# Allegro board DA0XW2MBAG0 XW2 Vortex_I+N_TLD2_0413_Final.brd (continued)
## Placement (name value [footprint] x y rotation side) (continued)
L3610  *0_6/S  [S0603]  216.82 152.46 270 top
L3611  *0_6/S  [S0603]  207.93 154.24 0 top
L3612  *0_6/S  [S0603]  207.93 155.76 0 top
L3613  PBY160808T-221Y-N  [R0603]  203.87 155.76 0 top
L3614  PBY160808T-221Y-N  [R0603]  203.87 154.24 0 top
L3615  PBY160808T-221Y-N  [R0603]  219.36 155.25 90 top
L3616  PBY160808T-221Y-N  [R0603]  219.36 152.46 90 top
L4000  4.7UH,+-20%,650MA_1210  [CHOKE-LQH32PN4R7NN0L]  19.79 123.41 270 bottom
L4100  *DLP0NSN900HL2L  [CHOKE-DLP0NSN900HL2L]  337.39 59.12 180 bottom
L6000  *0_6/S  [S0603]  260.41 22.49 90 top
L7000  MCM2012B900GBE  [FILTER-MCM2012B900GBE-4P]  18.75 108.68 180 top
L7001  MCM2012B900GBE  [FILTER-MCM2012B900GBE-4P]  19.21 87.34 180 top
L7002  MCM2012B900GBE  [FILTER-MCM2012B900GBE-4P]  353.73 75.66 90 bottom
L8000  *DLP0NSN900HL2L  [CHOKE-DLP0NSN900HL2L]  337.22 119.09 0 bottom
L8001  0.68U +-20%5A  [CHOKE-PCMB041B-1R0MS]  354.87 114.77 90 bottom
L9000  *DLP0NSN900HL2L  [CHOKE-DLP0NSN900HL2L]  237.01 77.31 45 bottom
LED6000  LED 3P WHITE/AMBER  [LEDLTW-326DSKF-5A-3P-SMT]  364.98 152.71 270 top
LED9000  *White_19-113/T1D-CP2Q2HY/3T  [LED19-113-T1D-CP2Q2HY-3T]  130.59 113.5 270 top
LED9002  WHITE  [LEDLTW-C191DS5]  299.88 31.69 270 bottom
LED9003  WHITE  [LEDLTW-C191DS5]  269.93 45.15 90 bottom
LED9004  *LED 4P WHITE/YELLOW  [LEDLTST-C195KGJRKT-4P]  319.23 42.52 180 top
NOREF  -  []  160.31 14.19 0 top
NOREF#2  -  [unnamed#2]  358.5 16.02 0 top
NOREF#3  -  []  231.81 -42.07 0 top
NOREF#4  -  []  135.03 14.44 0 top
NOREF#5  -  [unnamed#2]  18.32 43.14 0 top
NOREF#6  -  []  54.01 -54.77 0 top
NOREF#7  -  [unnamed#2]  36.48 147.41 0 top
NOREF#8  -  []  131.6 14.44 180 bottom
NOREF#9  -  [unnamed#2]  358.5 16.02 180 bottom
NOREF#10  -  [unnamed#2]  14 43.78 180 bottom
NOREF#11  -  []  140.37 15.88 180 bottom
NOREF#12  -  [unnamed#2]  25.56 147.41 180 bottom
PAD2  *pad-mws-vn-2nmp  [PAD-MWS-VN-2NMP]  368.46 109.18 0 top
PAD3  *pad-mws-vn-3nmp  [PAD-MWS-VN-3NMP]  185.99 85.06 0 top
PAD4  *pad-mws-vn-4nmp  [PAD-MWS-VN-4NMP]  369.21 109.18 180 bottom
PAD5  *SPAD-RE317X60NP  [SPAD-RE317X60NP]  363.78 0.76 0 top
PAD6  *SPAD-RE79X322NP  [SPAD-RE79X322NP]  6.64 88.81 180 bottom
PAD7  *SPAD-RE79X322NP  [SPAD-RE79X322NP]  6.65 107.31 180 bottom
PAD8  *SPAD-RE79X922NP  [SPAD-RE79X922NP]  6.37 57.62 180 bottom
PAD9  *SPAD-RE317X59NP  [SPAD-RE317X59NP]  363.85 0.75 0 bottom
PAD10  *SPAD-RE47X512NP  [SPAD-RE47X512NP]  366.35 58.6 180 bottom
PAD11  *SPAD-RE79X393NP  [SPAD-RE79X393NP]  365.14 96.16 0 bottom
PAD12  *SPAD-RE79X185NP  [SPAD-RE79X185NP]  366.47 131.96 180 bottom
PAD13  *SPAD-RE79X185NP  [SPAD-RE79X185NP]  366.47 115.32 180 bottom
PAD15  *SPAD-C236NPP  [SPAD-C236NPP]  127.98 100.5 0 top
PAD18  *SPAD-C138NP  [SPAD-C138NP]  331.22 21.76 0 top
PAD19  *SPAD-C157NP  [SPAD-C157NP]  189.48 15 0 top
PAD20  *SPAD-XW2A-1NP  [SPAD-XW2A-1NP]  40 148 0 top
PAD21  *SPAD-RE79X282NP  [SPAD-RE79X282NP]  185.99 53.57 180 bottom
PC8001  4.7U/6.3V_6  [C0603]  236.51 144.97 0 bottom
PC8002  0.1u/25V_4  [C0402]  239.05 152.11 180 bottom
PC8003  *4.7u/25V_6  [C0603]  239.05 153.63 180 bottom
PC8004  *4.7u/25V_6  [C0603]  239.02 153.38 180 top
PC8005  2200P/50V_4  [C0402]  239.02 150.84 180 top
PC8006  0.1u/25V_4  [C0402]  239.02 151.86 180 top
PC8007  0.1u/25V_4  [C0402]  241.08 144.97 270 bottom
PC8008  0.1u/16V_4  [C0402]  233.46 138.62 0 bottom
PC8009  22u/6.3V_8  [C0805]  240.57 142.17 270 bottom
PC8010  *22u/6.3V_8  [C0805]  238.41 134.33 180 bottom
PC8011  22u/6.3V_8  [C0805]  238.28 142.17 270 bottom
PC8012  *22u/6.3V_8  [C0805]  236 142.17 270 bottom
PC8014  *2200p/50V_4  [C0402]  243.49 151.14 0 bottom
PC8015  *0.047u/16V_4  [C0402]  234.73 148.65 270 bottom
PC8016  0.01U/50V_4  [C0402]  235.36 146.24 0 bottom
PC8017  *0.047u/16V_4  [C0402]  232.32 148.43 90 top
PC9001  *4.7u/25V_6  [C0603]  216.31 61.94 270 top
PC9002  2.2U/10V_4  [C0402]  206.79 57.46 0 bottom
PC9003  *4.7u/25V_6  [C0603]  226.6 63.34 270 top
PC9004  *4.7u/25V_6  [C0603]  220.63 62.7 270 top
PC9006  0.1u/25V_4  [C0402]  224.7 58.99 180 bottom
PC9007  *15u/25V_7343H1.9  [CC7343]  205.87 62.96 90 top
PC9008  *15u/25V_7343H1.9  [CC7343]  210.6 62.96 90 top
PC9009  0.22u/25V_4  [C0402]  211.23 55.68 270 bottom
PC9010  *4.7u/25V_6  [C0603]  214.28 61.94 270 top
PC9011  2200P/50V_4  [C0402]  219.23 58.99 180 bottom
PC9013  1u/25V_6  [C0603]  208.82 46.92 270 bottom
PC9014  *2200p/50V_4  [C0402]  201.63 67.73 90 bottom
PC9015  *0.22u/10V_4  [C0402]  202.37 50.99 0 bottom
PC9017  *4.7u/25V_6  [C0603]  188.75 56.48 0 bottom
PC9018  *4.7u/25V_6  [C0603]  188.75 58.51 0 bottom
PC9019  *4.7u/25V_6  [C0603]  188.75 61.71 0 bottom
PC9020  0.22u/25V_4  [C0402]  203.87 55.81 270 bottom
PC9022  0.1u/25V_4  [C0402]  188.96 60.21 0 bottom
PC9023  2200P/50V_4  [C0402]  198.53 58.99 180 bottom
PC9024  0.1u/16V_4  [C0402]  208.82 49.21 90 bottom
PC9026  220u/2V_7343H1.9  [CC7343]  213.01 75.62 0 top
PC9027  220u/2V_7343H1.9  [CC7343]  203.61 81.34 180 bottom
PC9028  220u/2V_7343H1.9  [CC7343]  213.52 81.34 0 bottom
PC9029  *220u/2V_7343H1.9  [CC7343]  193.71 81.34 180 bottom
PC9030  *2200p/50V_4  [C0402]  194.09 65.5 180 top
PC9031  *1500p/50V_4  [C0402]  210.85 49.21 270 bottom
PC9032  1500p/50V_4  [C0402]  212.76 49.61 180 bottom
PC9033  56p/50V_4  [C0402]  204.5 49.46 0 bottom
PC9034  *100p/50V_4  [C0402]  205.39 48.45 180 bottom
PC9035  56p/50V_4  [C0402]  206.28 49.46 180 bottom
PC9037  *4.7u/25V_6  [C0603]  200.31 62.19 270 top
PC9038  *4.7u/25V_6  [C0603]  202.34 62.19 270 top
PC9040  0.1u/25V_4  [C0402]  211.61 58.99 180 bottom
PC9041  0.22u/25V_4  [C0402]  216.44 50.22 90 top
PC9042  *100p/50V_4  [C0402]  203.49 47.43 180 bottom
PC9043  220u/2V_7343H1.9  [CC7343]  192.44 76.54 180 top
PC9044  1u/6.3V_4  [C0402]  219.23 57.08 270 bottom
PC9045  *2200p/50V_4  [C0402]  215.3 65.5 180 bottom
PC9046  2200P/50V_4  [C0402]  199.93 56.61 90 top
PC9211  820p/50V_4  [C0402]  211.87 53.14 270 bottom
PC9501  0.1u/16V_4  [C0402]  192.41 83.89 270 top
PC9502  0.1u/16V_4  [C0402]  197.9 82.64 180 top
PC9503  *10u/6.3V_6  [C0603]  192.46 87.49 90 top
PC9504  0.1u/16V_4  [C0402]  193.4 85.31 90 top
PC9505  0.1u/16V_4  [C0402]  197.9 86.29 90 top
PC9506  *10u/6.3V_6  [C0603]  198.15 89.21 180 top
PC9507  0.1u/16V_4  [C0402]  195.61 81.59 270 top
PC9508  *820p/50V_4  [C0402]  194.09 81.97 0 top
PC9509  *0.1u/16V_4  [C0402]  197.64 81.27 90 top
PC9510  *1000P/50V_4  [C0402]  194.49 88.23 270 top
PC9511  *1000P/50V_4  [C0402]  195.94 88.46 0 top
PC9512  10u/6.3V_6  [C0603]  199.3 80.84 270 top
PC9513  0.1u/16V_4  [C0402]  204.25 83.83 180 top
PC9514  22u/6.3V_6  [C0603]  202.85 87.56 90 top
PC9515  0.1u/16V_4  [C0402]  202.72 85.28 90 top
PC9516  0.1u/16V_4  [C0402]  205.39 84.29 0 bottom
PC9801  *2.2u/50V_6  [C0603]  189.01 50 180 bottom
PC9802  *2.2u/50V_6  [C0603]  201.23 50.13 90 top
PC9803  *0.1u/16V_4  [C0402]  200.31 52.03 0 bottom
PC9804  *0.01u/16V_4  [C0402]  200.31 54.07 180 bottom
PC9805  *2.2U/10V_4  [C0402]  200.31 52.03 180 top
PC9806  *2.2u/50V_6  [C0603]  199.8 50.13 270 top
PC9807  *2.2u/50V_6  [C0603]  191.93 49.87 90 bottom
PC9808  *2.2U/10V_4  [C0402]  198.15 55.72 90 bottom
PC9809  *0.1u/16V_4  [C0402]  197.14 55.72 270 bottom
PC10000  1u/25V_4  [C0402]  344.23 138.77 270 top
PC10001  1u/25V_4  [C0402]  344.33 135.22 270 top
PC10002  0.1u/25V_4  [C0402]  353.6 145 90 bottom
PC10003  0.1u/25V_4  [C0402]  351.03 139.79 270 bottom
PC10004  1u/25V_4  [C0402]  345.85 146.52 180 top
PC11000  *1u/25V_6  [C0603]  255.56 14.31 180 top
PC11001  0.1u/25V_4  [C0402]  255.05 12.66 0 top
PC11003  1u/25V_6  [C0603]  253.78 11.77 90 bottom
PC11004  0.1u/25V_4  [C0402]  252.38 11.39 270 bottom
PC11005  0.1u/25V_4  [C0402]  252.38 13.15 270 bottom
PC11006  10u/25V_8  [C0805]  244.51 22.95 0 top
PC11007  2.2u/16V_6  [C0603]  245.09 17.04 270 bottom
PC11008  10u/25V_8  [C0805]  243.72 19.4 0 bottom
PC11009  2200P/50V_4  [C0402]  253.65 16.35 90 bottom
PC11010  0.1u/25V_4  [C0402]  252.64 16.35 270 bottom
PC11011  1u/25V_6  [C0603]  249 16.27 270 bottom
PC11012  0.047u/25V_4  [C0402]  247.81 16.85 90 bottom
PC11013  *1000P/50V_4  [C0402]  252.76 9.87 180 bottom
PC11017  68u/25V_7343H2.9  [CC7343-3H]  214.03 17.64 90 bottom
PC11018  0.1u/25V_4  [C0402]  216.97 19.5 270 bottom
PC11019  *2200p/50V_4  [C0402]  237.47 18.53 270 bottom
PC11020  0.1u/25V_4  [C0402]  238.79 8.65 0 top
PC11021  0.1u/25V_4  [C0402]  238.11 7.3 90 top
PC11022  0.1u/25V_4  [C0402]  239.53 6.69 90 top
PC11023  100p/50V_4  [C0402]  250.5 6.85 90 bottom
PC11024  0.1u/16V_4  [C0402]  236 8.85 0 top
PC11025  100p/50V_4  [C0402]  250.6 9.13 90 top
PC11026  100p/50V_4  [C0402]  249.08 8.02 270 top
PC11027  220p/50V_4  [C0402]  246.16 10.28 0 top
PC12001  100p/50V_4  [C0402]  258.78 21.55 180 bottom
PC12002  0.22u/6.3V_4  [C0402]  260.56 23.59 180 bottom
PC12003  0.1u/25V_4  [C0402]  211.23 5.55 0 bottom
PC12004  0.1u/25V_4  [C0402]  209.25 17.59 0 bottom
PC12005  2200P/50V_4  [C0402]  209.25 18.73 0 bottom
PC12006  100p/50V_4  [C0402]  219.11 6.95 90 bottom
PC12007  100p/50V_4  [C0402]  221.14 6.95 90 bottom
PC12008  3900p/50V_4  [C0402]  296.32 39.59 270 top
PC12009  *0.1u/16V_4  [C0402]  297.09 36.79 270 top
PC12010  *220p/50V_4  [C0402]  226.73 11.9 0 top
PC12011  *1u/6.3V_4  [C0402]  229.04 11.83 270 top
PC13000  2.2U/6.3V_4  [C0402]  197.64 35.65 180 bottom
PC13003  2200P/50V_4  [C0402]  201.68 40.6 270 bottom
PC13004  0.1u/25V_4  [C0402]  204.5 44.16 270 bottom
PC13005  0.1u/25V_4  [C0402]  205.01 34.05 0 top
PC13006  0.22u/25V_4  [C0402]  192.79 38.52 90 top
PC13007  1u/6.3V_4  [C0402]  199.3 41.62 180 bottom
PC13011  100u/6.3V_3528H1.9  [C3528]  189.41 42.81 270 bottom
PC13012  0.1u/16V_4  [C0402]  189.52 38.95 180 bottom
PC13013  *2200p/50V_4  [C0402]  197.77 37.43 270 top
PC13014  *0.1u/16V_4  [C0402]  200.69 42.38 90 bottom
PC13015  2.2U/6.3V_4  [C0402]  220.12 46.7 0 bottom
PC13016  *4.7u/25V_6  [C0603]  214.92 43.68 270 bottom
PC13017  *4.7u/25V_6  [C0603]  213.47 43.68 270 bottom
PC13018  2200P/50V_4  [C0402]  216.14 44.03 270 bottom
PC13019  0.1u/25V_4  [C0402]  211.08 44.01 270 bottom
PC13020  0.1u/25V_4  [C0402]  210.06 44.01 270 bottom
PC13021  1u/6.3V_4  [C0402]  219.11 41.11 0 bottom
PC13022  0.22u/25V_4  [C0402]  220.78 43.4 270 bottom
PC13023  22u/6.3V_8  [C0805]  227.36 51.87 180 bottom
PC13024  22u/6.3V_8  [C0805]  222.79 53.81 0 bottom
PC13025  *22u/6.3V_8  [C0805]  220.25 48.96 0 bottom
PC13026  0.1u/16V_4  [C0402]  228.24 50.36 0 bottom
PC13027  22u/6.3V_8  [C0805]  222.79 51.78 0 bottom
PC13028  *200P/50V_4  [C0402]  217.3 44.92 90 top
PC13029  *0.1u/16V_4  [C0402]  217.71 40.48 270 bottom
PC13030  *4.7u/25V_6  [C0603]  207.88 38.37 180 bottom
PC13031  *4.7u/25V_6  [C0603]  209.33 35.73 270 bottom
PC13032  2200P/50V_4  [C0402]  207.42 36.79 0 bottom
PC13033  0.1u/25V_4  [C0402]  208.57 39.84 0 bottom
PC13034  0.1u/25V_4  [C0402]  210.09 40.22 90 bottom
PC13035  4.7U/6.3V_6  [C0603]  215.96 32.22 270 bottom
PC13036  0.1u/25V_4  [C0402]  216.06 34.63 180 top
PC13040  0.1u/16V_4  [C0402]  223.81 34.51 90 top
PC13041  100u/6.3V_3528H1.9  [C3528]  227.77 36.49 180 bottom
PC13042  *2200p/50V_4  [C0402]  212.25 39.97 270 bottom
PC13043  *0.1u/16V_4  [C0402]  213.65 32.09 270 bottom
PC13044  0.1u/16V_4  [C0402]  214.66 32.09 90 bottom
PC14000  1U/6.3V_4  [C0402]  95.03 64.73 90 top
PC14001  0.1U/25V_4  [C0402]  73.77 51.81 0 top
PC14002  0.1U/25V_4  [C0402]  97.95 66.64 180 top
PC14003  *4.7u/25V_6  [C0603]  97.95 69.18 0 top
PC14004  *4.7u/25V_6  [C0603]  97.95 71.21 0 top
PC14005  2200P/50V_4  [C0402]  97.95 67.65 180 top
PC14006  0.22u/25V_4  [C0402]  103.28 60.97 0 top
PC14007  68P/50V_4  [C0402]  91.9 66.46 270 top
PC14008  10U/6.3V_6  [C0603]  93.76 64.23 270 top
PC14009  0.1U/16V_4  [C0402]  102.75 49.54 0 top
PC14010  22U/6.3V_8  [C0805]  102.9 46.75 180 top
PC14011  *22U/6.3V_8  [C0805]  96.76 50.21 0 top
PC14012  *22U/6.3V_8  [C0805]  96.76 48.15 0 top
PC14013  *22u/6.3V_8  [C0805]  96.78 46.14 0 top
PC14014  0.1U/16V_4  [C0402]  92.74 61.94 270 top
PC14015  *0.033U/10V_4  [C0402]  94.39 62.32 0 top
PC14016  *2200P/50V_4  [C0402]  98.33 65.5 90 bottom
PC14017  *0.1U/16V_4  [C0402]  101.63 69.81 0 top
PC14018  1u/6.3V_4  [C0402]  101.63 67.78 0 top
PC14019  *220P/50V_4  [C0402]  101.63 65.75 180 top
PC15000  1U/6.3V_4  [C0402]  206.53 31.43 0 bottom
PC15001  0.1U/25V_4  [C0402]  208.9 28.51 270 bottom
PC15002  *4.7u/25V_6  [C0603]  215.02 26.38 90 bottom
PC15003  0.1U/25V_4  [C0402]  214.54 29.17 270 bottom
PC15004  *4.7u/25V_6  [C0603]  216.47 26.38 90 bottom
PC15005  2200P/50V_4  [C0402]  213.52 29.17 90 bottom
PC15006  0.22u/25V_4  [C0402]  202.34 30.54 90 bottom
PC15007  0.22U/10V_4  [C0402]  206.41 24.19 180 bottom
PC15008  0.1U/16V_4  [C0402]  190.41 26.63 90 bottom
PC15009  22U/6.3V_8  [C0805]  191.42 34.05 270 bottom
PC15010  *22U/6.3V_8  [C0805]  193.99 26.61 90 bottom
PC15011  *22U/6.3V_8  [C0805]  191.95 26.61 90 bottom
PC15012  *2200P/50V_4  [C0402]  203.87 32.48 90 top
PC16000  1U/6.3V_4  [C0402]  291.73 15.51 90 top
PC16001  *4.7u/25V_6  [C0603]  294.65 8.98 180 top
PC16002  2200P/50V_4  [C0402]  294.62 12.46 0 top
PC16003  0.1U/25V_4  [C0402]  296.83 8.5 270 top
PC16004  0.1U/25V_4  [C0402]  294.62 13.43 0 top
PC16005  *4.7u/25V_6  [C0603]  294.65 10.99 180 top
PC16006  0.22u/25V_4  [C0402]  291.57 19.7 270 top
PC16007  0.1U/16V_4  [C0402]  291.24 26 0 top
PC16008  22U/6.3V_8  [C0805]  292.13 23.84 90 top
PC16009  *22U/6.3V_8  [C0805]  294.8 23.84 90 bottom
PC16010  *22U/6.3V_8  [C0805]  292.77 23.84 90 bottom
PC16011  *2200P/50V_4  [C0402]  295.13 14.87 270 bottom
PC16012  *0.1U/16V_4  [C0402]  297.8 14.49 270 top
PC16013  0.1u/16V_4  [C0402]  103.28 21.55 270 top
PC16014  10u/6.3V_6  [C0603]  104.55 21.55 90 top
PC16015  *10u/6.3V_6  [C0603]  105.16 33.11 180 top
PC16016  0.1u/16V_4  [C0402]  105.42 36.03 0 top
PC16017  *0.1u/16V_4  [C0402]  101.94 22.09 270 top
PC16018  10U/6.3V_6  [C0603]  105.16 34.63 180 top
PC16019  1u/6.3V_4  [C0402]  105.82 28.28 270 top
PC17000  1U/6.3V_4  [C0402]  181.9 150.2 270 bottom
PC17001  0.1U/25V_4  [C0402]  184.82 152.87 0 bottom
PC17002  *4.7u/25V_6  [C0603]  184.31 157.44 180 bottom
PC17003  *4.7u/25V_6  [C0603]  184.31 155.41 180 bottom
PC17004  0.1U/25V_4  [C0402]  180.88 157.44 180 bottom
PC17005  2200P/50V_4  [C0402]  184.82 153.89 0 bottom
PC17006  *0.1U/16V_4  [C0402]  188.63 151.35 180 bottom
PC17007  0.22u/25V_4  [C0402]  181.64 146.52 90 bottom
PC17008  0.1U/16V_4  [C0402]  190.91 130.49 0 bottom
PC17009  22U/6.3V_8  [C0805]  190.1 139.05 180 bottom
PC17010  *22U/6.3V_8  [C0805]  190.1 136.77 180 bottom
PC17011  *22U/6.3V_8  [C0805]  191.55 132.04 180 bottom
PC17012  *2200P/50V_4  [C0402]  184.94 151.47 90 top
PC18000  4.7u/6.3V_6  [C0603]  304.58 61.3 270 top
PC18001  2200p/50V_4  [C0402]  307.63 69.43 90 top
PC18002  0.1u/25V_4  [C0402]  306.61 69.43 90 top
PC18003  *4.7u/25V_6  [C0603]  309.15 69.18 270 top
PC18004  *4.7u/25V_6  [C0603]  311.18 69.18 270 top
PC18005  0.1u/25V_4  [C0402]  311.89 63.34 180 top
PC18006  0.1u/25V_4  [C0402]  300.26 62.45 270 top
PC18007  0.1u/16V_4  [C0402]  291.75 61.86 90 top
PC18008  22u/6.3V_8  [C0805]  290.48 67.02 270 bottom
PC18009  22u/6.3V_8  [C0805]  290.48 67.02 270 top
PC18010  22u/6.3V_8  [C0805]  288.45 67.02 270 top
PC18011  *22u/6.3V_8  [C0805]  285.15 64.48 0 top
PC18012  22u/6.3V_8  [C0805]  290.23 61.94 90 top
PC18013  *2200p/50V_4  [C0402]  301.91 66.13 90 bottom
PC18014  0.1u/16V_4  [C0402]  307.88 63.84 0 top
PC18015  0.1u/16V_4  [C0402]  305.8 61.61 90 top
PC19000  4.7u/6.3V_4  [C0402_2]  132.62 148.17 90 bottom
PC19001  0.1u/16V_4  [C0402]  123.35 154.01 270 top
PC19002  0.1u/16V_4  [C0402]  130.84 152.62 180 top
PC19003  1u/6.3V_4  [C0402]  124.37 154.01 90 bottom
PC19004  0.01U/50V_4  [C0402]  131.99 146.78 0 bottom
PC19005  *0.1u/16V_4  [C0402]  131.93 151.47 270 bottom
PC19006  *0.1u/6.3V_2  [C0201]  126.65 141.65 180 bottom
PC19007  *0.1u/16V_4  [C0402]  131.96 153.25 270 bottom
PC19008  *0.1u/6.3V_2  [C0201]  124.24 141.01 270 bottom
PC19009  220p/50V_4  [C0402]  126.14 146.39 90 top
PC19010  220p/50V_4  [C0402]  124.75 146.9 0 top
PC19011  47p/50V_4  [C0402]  124.75 149.95 0 top
PC19012  *0.1u/16V_4  [C0402]  121.19 144.11 90 bottom
PC19013  330p/50V_4  [C0402]  129.83 148.81 180 top
PC19014  1u/6.3V_4  [C0402]  133.76 146.78 0 bottom
PC20000  1u/6.3V_4  [C0402]  140.62 153.51 270 top
PC20001  *4.7u/25V_6  [C0603]  136.94 146.9 180 top
PC20002  *4.7u/25V_6  [C0603]  144.3 149.7 90 top
PC20003  *4.7u/25V_6  [C0603]  142.27 149.7 90 top
PC20004  2200P/50V_4  [C0402]  143.54 149.44 90 bottom
PC20005  0.1u/50V_4  [C0402]  142.58 149.44 90 bottom
PC20006  68u/25V_7343H2.9  [CC7343-3H]  147.58 156.91 0 bottom
PC20007  68u/25V_7343H2.9  [CC7343-3H]  164.55 157.06 0 bottom
PC20008  68u/25V_7343H2.9  [CC7343-3H]  172.63 155.08 270 bottom
PC20009  0.1u/50V_4  [C0402]  145.83 154.49 90 top
PC20010  *2200p/50V_4  [C0402]  141.51 145.76 180 top
PC20011  0.22u/25V_4  [C0402]  140.67 141.95 180 top
PC20012  *0.1u/50V_4  [C0402]  141.64 159.35 180 top
PC20013  *4.7u/25V_6  [C0603]  155.4 149.28 90 top
PC20014  *4.7u/25V_6  [C0603]  138.26 150 90 top
PC20015  *4.7u/25V_6  [C0603]  152.31 149.32 90 top
PC20016  2200P/50V_4  [C0402]  150.65 149.66 90 top
PC20017  0.1u/50V_4  [C0402]  149.64 149.66 90 top
PC20018  1u/6.3V_4  [C0402]  148.11 154.62 270 top
PC20019  0.1u/50V_4  [C0402]  153.83 154.49 90 top
PC20020  *2200p/50V_4  [C0402]  150.02 145.51 180 top
PC20021  0.22u/25V_4  [C0402]  149.89 141.54 90 top
PC20022  *0.1u/50V_4  [C0402]  148.62 159.06 180 top
PC20023  220u/2V_7343H1.9  [CC7343]  167.67 133.57 0 bottom
PC20024  220u/2V_7343H1.9  [CC7343]  158.02 133.57 180 bottom
PC20025  220u/2V_7343H1.9  [CC7343]  148.37 133.57 180 bottom
PC20026  220u/2V_7343H1.9  [CC7343]  171.86 133.54 0 top
PC20027  *4.7u/25V_6  [C0603]  162.16 149.44 90 top
PC20028  *4.7u/25V_6  [C0603]  169.45 149.44 90 top
PC20029  *4.7u/25V_6  [C0603]  160.18 149.44 90 top
PC20030  2200P/50V_4  [C0402]  160.56 149.44 90 bottom
PC20031  0.1u/50V_4  [C0402]  161.58 149.44 90 bottom
PC20032  1u/6.3V_4  [C0402]  155.99 154.62 270 top
PC20033  0.1u/50V_4  [C0402]  161.7 154.49 90 top
PC20034  *2200p/50V_4  [C0402]  158.4 145.51 180 top
PC20035  0.22u/25V_4  [C0402]  158.78 141.54 90 top
PC20036  *0.1u/50V_4  [C0402]  156.5 159.06 180 top
PC20037  *4.7u/25V_6  [C0603]  164.62 149.41 90 top
PC20038  *4.7u/25V_6  [C0603]  173.51 149.16 90 top
PC20039  *4.7u/25V_6  [C0603]  171.48 149.16 90 top
PC20040  2200P/50V_4  [C0402]  170.59 149.44 90 bottom
PC20041  0.1u/50V_4  [C0402]  169.58 149.44 90 bottom
PC20042  1u/6.3V_4  [C0402]  164.12 154.62 270 top
PC20043  0.1u/50V_4  [C0402]  169.83 154.49 90 top
PC20044  *2200p/50V_4  [C0402]  168.18 145.51 180 top
PC20045  0.22u/25V_4  [C0402]  167.93 141.41 90 top
PC20046  *0.1u/50V_4  [C0402]  164.62 159.06 180 top
PC20047  *0.1u/16V_4  [C0402]  184.82 153.13 0 top
PC21000  10u/25V_8  [C0805]  118.52 123.97 90 bottom
PC21001  10u/25V_8  [C0805]  116.49 123.97 90 bottom
PC21003  *10u/25V_8  [C0805]  118.7 123.94 90 top
PC21004  1u/25V_4  [C0402]  124.62 125.19 90 bottom
PC21005  2200P/50V_4  [C0402]  116.87 126.07 0 bottom
PC21006  0.1u/50V_4  [C0402]  116.87 127.09 0 bottom
PC21007  68u/25V_7343H2.9  [CC7343-3H]  116.97 117.64 90 bottom
PC21008  *15u/25V_7343H1.9  [CC7343]  121.83 134.36 90 bottom
PC21009  1u/6.3V_4  [C0402]  122.97 126.96 180 bottom
PC21010  1u/25V_4  [C0402]  125.13 126.58 180 bottom
PC21011  *2200p/50V_4  [C0402]  122.71 118.96 270 bottom
PC21012  *10u/25V_8  [C0805]  119.51 112.03 90 top
PC21013  10u/25V_8  [C0805]  119.51 112.03 90 bottom
PC21015  10u/25V_8  [C0805]  117.53 111.01 90 bottom
PC21016  1u/25V_4  [C0402]  125.46 113.12 90 bottom
PC21017  2200P/50V_4  [C0402]  114.89 112.05 90 bottom
PC21018  0.1u/50V_4  [C0402]  115.91 111.67 90 bottom
PC21019  220u/2V_7343H1.9  [CC7343]  128.3 123.53 180 top
PC21020  220u/2V_7343H1.9  [CC7343]  129.45 117.44 180 bottom
PC21021  1u/6.3V_4  [C0402]  123.73 114.9 180 bottom
PC21022  1u/25V_4  [C0402]  126.12 114.59 180 bottom
PC21023  *2200p/50V_4  [C0402]  125.51 107.53 0 bottom
PC21024  10u/25V_8  [C0805]  176.94 152.01 0 bottom
PC21025  10u/25V_8  [C0805]  176.94 154.01 0 bottom
PC21026  1u/25V_4  [C0402]  177.71 145.93 0 bottom
PC21027  2200P/50V_4  [C0402]  176.94 156.55 0 bottom
PC21028  0.1u/50V_4  [C0402]  176.94 155.54 0 bottom
PC21029  1u/6.3V_4  [C0402]  179.99 147.25 0 bottom
PC21030  1u/25V_4  [C0402]  179.1 145.55 90 bottom
PC21031  22u/6.3V_8  [C0805]  178.47 130.77 180 bottom
PC21032  22u/6.3V_8  [C0805]  178.42 132.81 180 bottom
PC21033  *22u/6.3V_8  [C0805]  174.4 132.68 0 bottom
PC21034  *22u/6.3V_8  [C0805]  174.4 134.71 0 bottom
PC21035  *2200p/50V_4  [C0402]  173.82 148.39 180 bottom
PC22000  0.1U/16V_4  [C0402]  38.13 62.7 270 top
PC22001  0.1U/16V_4  [C0402]  282.1 34.51 270 top
PC22002  0.1U/16V_4  [C0402]  286.67 34.63 270 top
PC22003  0.1U/16V_4  [C0402]  42.7 62.7 270 top
PC22004  *10U/6.3V_6  [C0603]  282.1 38.95 0 top
PC22005  0.1U/16V_4  [C0402]  281.97 37.68 0 top
PC22006  0.1U/16V_4  [C0402]  286.8 37.68 180 top
PC22007  *10U/6.3V_6  [C0603]  286.8 38.95 180 top
PC22008  *10U/6.3V_6  [C0603]  38.01 66.51 0 top
PC22009  0.1U/16V_4  [C0402]  38.13 64.48 90 top
PC22010  0.1U/16V_4  [C0402]  42.7 64.48 90 top
PC22011  *10U/6.3V_6  [C0603]  42.96 66.13 180 top
PC22012  0.1U/16V_4  [C0402]  284.39 31.71 90 top
PC22013  0.1U/16V_4  [C0402]  40.42 59.91 90 top
PC22014  *0.1U/16V_4  [C0402]  285.91 32.09 180 top
PC22015  *0.1U/16V_4  [C0402]  41.94 60.29 180 top
PC22016  1000P/50V_4  [C0402]  284 38.27 270 top
PC22017  1000P/50V_4  [C0402]  284.97 38.27 270 top
PC22018  *0.1U/16V_4  [C0402]  38.77 60.39 0 top
PC22019  1000P/50V_4  [C0402]  39.91 67.02 270 top
PC22020  1000P/50V_4  [C0402]  40.93 67.02 270 top
PC22021  *0.1U/16V_4  [C0402]  282.86 32.09 0 top
PC22022  *0.1U/16V_4  [C0402]  263.68 37.68 90 top
PC22023  0.1U/16V_4  [C0402]  266.61 40.73 270 top
PC22024  0.1U/16V_4  [C0402]  264.83 37.68 90 top
PC22025  0.1U/16V_4  [C0402]  266.73 43.52 180 top
PC22026  0.1U/16V_4  [C0402]  262.03 40.73 270 top
PC22027  1000P/50V_4  [C0402]  263.86 45.05 270 top
PC22028  1000P/50V_4  [C0402]  264.83 45.05 270 top
PC22029  *0.1U/16V_4  [C0402]  265.84 37.68 90 top
PC22030  *10U/6.3V_6  [C0603]  263.68 47.08 180 top
PC22031  0.1U/16V_4  [C0402]  261.07 41.75 90 top
PC22032  *10U/6.3V_6  [C0603]  266.73 45.18 180 top
PC23005  0.1U/16V_4  [C0402]  190.23 134.89 180 top
PC23006  0.1U/16V_4  [C0402]  190.28 140.88 180 top
PC23007  0.1U/16V_4  [C0402]  187.26 141.21 270 top
PC23008  *10U/6.3V_6  [C0603]  188.5 140.76 270 top
PC23009  0.1U/16V_4  [C0402]  112.17 96.32 180 bottom
PC23010  *10U/6.3V_6  [C0603]  112.3 97.88 180 bottom
PC23011  0.1U/16V_4  [C0402]  122.21 91.25 0 top
PC23012  0.1U/16V_4  [C0402]  119.29 93.56 270 top
PC23013  *10U/6.3V_6  [C0603]  117.89 93.82 270 top
PC23014  0.1U/16V_4  [C0402]  203.23 11.06 270 bottom
PC23015  0.1U/16V_4  [C0402]  196.5 15.79 90 bottom
PC23016  *10U/6.3V_6  [C0603]  205.82 9.79 180 bottom
PC23017  1u/6.3V_4  [C0402]  199.88 13.15 0 bottom
PC23018  *0.1u/16V_4  [C0402]  198.86 15.64 90 bottom
PC24000  *0.1U/16V_4  [C0402]  191.55 158.08 270 top
PC25000  1000P/50V_4  [C0402]  297.21 35.65 180 bottom
PC25001  0.22U/10V_4  [C0402]  295.18 34.63 0 bottom
PC25002  3300P/50V_4  [C0402]  293.78 44.57 0 bottom
PC25003  0.1U/16V_4  [C0402]  299.47 40.48 270 bottom
PC25004  *0.01U/50V_4  [C0402]  299.24 35.65 0 bottom
PC25005  1U/6.3V_4  [C0402]  270.03 40.6 90 bottom
PC25007  *220u/2.5V_3528H1.9  [C3528]  237.27 137.12 180 bottom
PC25008  0.1u/25V_4  [C0402]  346.23 139.05 90 top
PC25009  0.1u/25V_4  [C0402]  332.95 137.99 90 bottom
PC25010  *15u/25V_3528H1.1  [C3528]  244.74 20.16 0 top
PC25011  15u/25V_3528H1.1  [C3528]  211.11 27.14 90 bottom
PC25012  15u/25V_3528H1.1  [C3528]  102.5 78.5 180 top
PC25013  *15u/25V_3528H1.1  [C3528]  203.87 38.7 90 bottom
PC25014  0.1u/16V_4  [C0402]  227.92 85.05 270 bottom
PCN10000  040003HR005BA19ZL  [DCJK-040003HR005BA19ZL-5P]  362.74 145.06 90 top
PCN12000  C144RN-K0823-L  [BAT-C144RN-K0823-L-8P-L-SMT]  221.73 2.2 180 bottom
PD1  P4SMAFJ20A  [D-3_8X2_5]  346.49 142.48 90 bottom
PD2  PDZ5.1B  [DSM]  332.26 145.2 0 bottom
PD3  PDZ5.1B  [DSM]  332.69 142.58 90 top
PD9002  RB500V-40  [DSM]  214.96 52.26 90 top
PD9005  RB500V-40  [DSM]  213.18 52.26 90 top
PD9501  *RB500V-40  [DSM]  198.51 84.88 180 bottom
PD11000  P4SMAFJ20A  [D-3_8X2_5]  303.03 7.41 0 top
PD11001  MEW316-D3-G  [DSM]  252 14.15 0 top
PD11002  *UDZ8V2B-7  [DSM]  244.55 17.37 180 top
PD11003  MEW316-D3-G  [DSM]  252 16.05 0 top
PD11004  SX34  [D-4_3X2_7]  210.67 7.76 180 bottom
PD11005  MEW316-D3-G  [DSM]  252.18 14.66 0 bottom
PD11006  PDZ5.1B  [DSM]  220.88 20.89 90 top
PD11007  MEW316-D3-G  [DSM]  255.43 10.25 0 top
PD11008  BAT54CW  [UMT_213-3-1_3]  257.33 7.84 0 top
PD12000  BAV99-7-F  [SOT23_213-3_3-2]  223.93 9.74 90 bottom
PD12001  BAV99-7-F  [SOT23_213-3_3-2]  220.12 9.74 90 bottom
PD25000  BAT54AW-L  [SOT323_213-2_1-1_3-3P]  294.8 30.57 270 bottom
PJP13001  *POWER_JP/S  [SHORT-SOLDERJUMPER-3]  225.97 52.92 270 bottom
PJP13002  *POWER_JP/S  [SHORT-SOLDERJUMPER-3]  224.44 39.89 180 bottom
PJP14000  *POWER_JP/S  [SHORT-SOLDERJUMPER-3]  99.73 44.54 270 top
PJP15000  *POWER_JP/S  [SHORT-SOLDERJUMPER-3]  190.15 30.85 180 bottom
PJP16000  *POWER_JP/S  [SHORT-SOLDERJUMPER-3]  291.39 28.21 180 top
PJP16001  *POWER_JP/S  [SHORT-SOLDERJUMPER-3]  102.27 36.79 180 top
PJP17000  *POWER_JP/S  [SHORT-SOLDERJUMPER-3]  188.63 131.25 45 bottom
PJP18000  *short-solderjumper-3  [SHORT-SOLDERJUMPER-3]  285.15 66.77 315 top
PL2100  0.47uH_7x7x3  [CHOKE-PCMC063T-3R3MN-SMT]  129.67 123.23 0 bottom
PL2101  0.47uH_7x7x3  [CHOKE-PCMC063T-3R3MN-SMT]  130.59 111.67 0 bottom
PL2102  0.68uH_7x7x3  [CHOKE-PCMC063T-3R3MN-SMT]  175.67 140.9 270 bottom
PL8001  0.68uH_7x7x3  [CHOKE-PCMC063T-3R3MN-SMT]  245.02 145.42 270 bottom
PL9001  0.22uH_7x7x3  [CHOKE-PCMC063T-3R3MN-SMT]  205.7 72.63 90 bottom
PL9004  0.22uH_7x7x3  [CHOKE-PCMC063T-3R3MN-SMT]  195.38 72.66 90 bottom
PL9005  0.22uH_7x7x3  [CHOKE-PCMC063T-3R3MN-SMT]  214.33 72.61 90 bottom
PL9501  2.2uH_2.5x2.0x1.2  [L2_5X2-1_2H]  200.44 85.02 0 top
PL11000  2.2uH_10x10x4  [L10X10-3_8]  228.38 18.12 180 bottom
PL12000  *Short_0805  [S0805]  217.13 5.91 270 bottom
PL12001  *Short_0805  [S0805]  215.14 5.91 270 bottom
PL12002  *Short_0805  [S0805]  213.19 5.91 270 bottom
PL13001  2.2uH_7x7x3  [CHOKE-PCMC063T-3R3MN-SMT]  194.6 39.74 90 bottom
PL13002  *0_8/S  [S0805]  211.11 42.13 0 bottom
PL13003  2.2uH_7x7x3  [CHOKE-PCMC063T-3R3MN-SMT]  225.33 46.19 90 bottom
PL13004  *Short_0805  [S0805]  205.65 40.1 0 bottom
PL13005  1.5uH_7x7x3  [CHOKE-PCMC063T-3R3MN-SMT]  220.63 35.65 0 bottom
PL14001  1uH_7x7x3  [CHOKE-PCMC063T-3R3MN-SMT]  100.49 55.72 270 top
PL15001  2.2uH_7x7x3  [CHOKE-PCMC063T-3R3MN-SMT]  197.01 31.73 180 bottom
PL16000  *0_8/S  [S0805]  294.65 6.97 180 top
PL16001  2.2uH_7x7x3  [CHOKE-PCMC063T-3R3MN-SMT]  296.54 22.05 90 top
PL17000  *0_8/S  [S0805]  181.01 158.97 0 bottom
PL17001  1uH_7x7x3  [CHOKE-PCMC063T-3R3MN-SMT]  185.83 144.24 270 bottom
PL18000  *Short_0805  [S0805]  311.82 65.75 90 top
PL18001  1uH_7x7x3  [CHOKE-PCMC063T-3R3MN-SMT]  296.07 65.57 180 top
PL20000  0.24uH_7x7x3  [CHOKE-PCMC063T-3R3MN-SMT]  141.76 140.77 270 bottom
PL20001  0.24uH_7x7x3  [CHOKE-PCMC063T-3R3MN-SMT]  149.26 140.77 270 bottom
PL20002  0.24uH_7x7x3  [CHOKE-PCMC063T-3R3MN-SMT]  158.15 140.77 270 bottom
PL20003  0.24uH_7x7x3  [CHOKE-PCMC063T-3R3MN-SMT]  167.29 140.77 270 bottom
PQ8002  2N7002K  [SOT23_213-3_3-2]  232.57 145.6 90 bottom
PQ8003  DMG1012T-7  [D-SOT523_213-1_6-1]  231.88 150.68 0 bottom
PQ8004  *DMG1012T-7  [D-SOT523_213-1_6-1]  233.71 150.97 270 top
PQ9001  AOE6930  [POWER-5X6-1_27-10P]  211.61 62.8 180 bottom
PQ9004  AOE6930  [POWER-5X6-1_27-10P]  198.53 62.8 180 bottom
PQ9005  AOE6930  [POWER-5X6-1_27-10P]  219.23 62.8 180 bottom
PQ9006  *AOE6930  [POWER-5X6-1_27-10P]  206.15 62.8 180 bottom
PQ9007  *AOE6930  [POWER-5X6-1_27-10P]  193.07 62.8 180 bottom
PQ9008  *AOE6930  [POWER-5X6-1_27-10P]  224.7 62.8 180 bottom
PQ9501  2N7002K  [SOT23_213-3_3-2]  189.39 69.65 180 top
PQ9502  DMG1012T-7  [D-SOT523_213-1_6-1]  190.15 72.83 90 top
PQ10000  AONR21357  [POWER-3_1X3_1-65-5P]  341.66 138.14 0 top
PQ10001  AONR21357  [POWER-3_1X3_1-65-5P]  341.66 134.58 0 top
PQ10002  BSS84  [SOT23_213-3_3-2]  342.93 138.27 180 bottom
PQ10003  BSS84  [SOT23_213-3_3-2]  335.31 138.52 270 bottom
PQ10004  2N7002KDW  [SOT363-2_1-65-6P]  338.41 137.38 270 bottom
PQ10005  2N7002KDW  [SOT363-2_1-65-6P]  332.7 141.42 270 bottom
PQ10006  EMB03P03H  [POWER-5_2X5_55-1_27-5P]  341.41 142.97 0 bottom
PQ10007  EMB03P03H  [POWER-5_2X5_55-1_27-5P]  344.79 142.97 0 top
PQ10008  PMBT3906  [SOT23_213-3_3-2]  354.21 138.01 90 bottom
PQ10009  PJC7439  [UMT_213-3-1_3]  345.24 147.49 270 bottom
PQ10010  PMBT3906  [SOT23_213-3_3-2]  346.74 137.38 180 bottom
PQ10011  AONR21357  [POWER-3_1X3_1-65-5P]  337.34 138.14 180 top
PQ10012  AONR21357  [POWER-3_1X3_1-65-5P]  337.34 134.58 180 top
PQ10013  EMB03P03H  [POWER-5_2X5_55-1_27-5P]  338.03 142.97 180 top
PQ10014  BSS84  [SOT23_213-3_3-2]  341.91 148.17 270 bottom
PQ10015  BSS84  [SOT23_213-3_3-2]  336.07 143.78 0 bottom
PQ10016  BSS84  [SOT23_213-3_3-2]  339.6 148.17 90 top
PQ10017  MMDT2907A-7-F  [SOT363-2_1-65-6P]  338.83 147.54 90 bottom
PQ10018  MMDT2907A-7-F  [SOT363-2_1-65-6P]  335.31 147.64 270 bottom
PQ10019  MMDT2907A-7-F  [SOT363-2_1-65-6P]  336.47 148.35 270 top
PQ11000  EMB03P03H  [POWER-5_2X5_55-1_27-5P]  220 23.84 90 bottom
PQ11001  AON6354L  [POWER-5_2X5_55-1_27-5P]  245.65 23.2 180 bottom
PQ11002  AON6354L  [POWER-5_2X5_55-1_27-5P]  239.3 22.95 270 bottom
PQ11003  2N7002K  [SOT23_213-3_3-2]  254.79 5.04 180 top
PQ11004  BSS84  [SOT23_213-3_3-2]  224.82 21.55 270 top
PQ11005  MMDT2907A-7-F  [SOT363-2_1-65-6P]  224.82 18.38 0 top
PQ12003  2N7002K  [SOT23_213-3_3-2]  269.27 5.04 0 top
PQ12004  *2N7002K  [SOT23_213-3_3-2]  267.75 8.98 180 bottom
PQ12005  *BSS84  [SOT23_213-3_3-2]  299.42 37.61 0 top
PQ12006  *PMBT3906  [SOT23_213-3_3-2]  303.23 35.9 90 top
PQ12007  PMBT3906  [SOT23_213-3_3-2]  303.13 39.74 90 top
PQ12008  2N7002K  [SOT23_213-3_3-2]  291.75 39.97 270 top
PQ12009  PMST3904  [UMT_213-3-1_3]  297.77 33.62 90 top
PQ12011  *PMBT3906  [SOT23_213-3_3-2]  227.31 15.43 270 top
PQ12012  *PMBT3906  [SOT23_213-3_3-2]  231.3 15.08 180 top
PQ14000  2N7002K  [SOT23_213-3_3-2]  90.08 69.18 270 top
PQ14001  *2N7002K  [SOT23_213-3_3-2]  101.25 72.1 0 bottom
PQ14002  2N7002KDW  [SC70-2_1-65-6P]  87.79 62.83 0 top
PQ20000  AOE6930  [POWER-5X6-1_27-10P]  139.35 148.65 0 bottom
PQ20001  AOE6930  [POWER-5X6-1_27-10P]  148.24 148.65 0 bottom
PQ20002  AOE6930  [POWER-5X6-1_27-10P]  157.13 148.65 0 bottom
PQ20003  AOE6930  [POWER-5X6-1_27-10P]  166.28 148.65 0 bottom
PQ23003  ME2320D-G  [SOT23_213-3_3-2]  190.46 137.53 90 top
PQ23004  ME2320D-G  [SOT23_213-3_3-2]  190 143.25 90 top
PQ23005  2N7002KDW  [SC70-2_1-65-6P]  109.08 90.56 90 top
PQ23006  ME2320D-G  [SOT23_213-3_3-2]  121.98 94.07 180 top
PQ23007  2N7002KDW  [SC70-2_1-65-6P]  113.19 90.61 90 top
PQ23008  *2N7002KDW  [SC70-2_1-65-6P]  113.19 90.61 90 bottom
PQ24000  *2N7002K  [SOT23_213-3_3-2]  192.28 157.54 90 bottom
PQ26000  2N7002K  [SOT23_213-3_3-2]  122.84 100.26 180 bottom
PQ26001  PMBT3906  [SOT23_213-3_3-2]  119.03 100.26 90 bottom
PQ26002  PMBT3904  [SOT23_213-3_3-2]  117.63 96.32 90 bottom
PQ26003  2N7002K  [SOT23_213-3_3-2]  122.84 92.51 180 bottom
PQ26004  PMBT3906  [SOT23_213-3_3-2]  119.03 92.59 90 bottom
PQ26005  PMBT3904  [SOT23_213-3_3-2]  117.63 88.86 90 bottom
PQ26006  PJE138K  [SOT523_213-1_6-1-0_6H]  343.97 149.11 90 top
PR8001  113K_1%_4  [R0402]  237.01 151.7 180 bottom
PR8002  1_5%_6  [R0603]  239.17 144.64 180 bottom
PR8003  *0_4/S  [S0402]  235.36 147.25 180 bottom
PR8004  *2.2_5%_6  [R0603]  245.78 151.14 0 bottom
PR8005  *Short_0201  [S0201]  235.62 148.65 270 bottom
PR8006  *Short_0201  [S0201]  233.46 137.63 0 bottom
PR8007  *0_4/S  [S0402]  233.71 148.65 90 bottom
PR8008  8.25K_1%_4  [R0402]  234.6 150.68 270 bottom
PR8009  12K_1%_4  [R0402]  235.62 150.68 270 bottom
PR8010  100K_1%_4  [R0402]  232.19 149.03 0 bottom
PR8012  1M_5%_4  [R0402]  232.19 148.01 180 bottom
PR8013  *42.2K_1%_4  [R0402]  233.59 150.68 270 bottom
PR8018  *0_5%_4  [R0402]  231.17 150.2 90 top
PR8021  *100K_1%_4  [R0402]  231.3 148.43 90 top
PR8022  22_5%_8  [R0805]  231.81 142.3 180 bottom
PR8023  *Short_0402  [S0402]  233.46 138.65 0 top
PR9001  1_5%_6  [R0603]  207.3 46.92 270 bottom
PR9002  1_5%_6  [R0603]  209.2 57.46 0 bottom
PR9003  1_5%_6  [R0603]  212.76 55.68 270 bottom
PR9004  499K_1%_4  [R0402]  207.8 49.21 270 bottom
PR9005  *2.2_5%_6  [R0603]  201.56 69.92 90 bottom
PR9006  10K_1%_4  [R0402]  202.22 52.29 180 bottom
PR9011  10K_1%_4  [R0402]  202.22 48.73 0 bottom
PR9012  1_5%_6  [R0603]  202.6 53.78 0 bottom
PR9013  *0_4/S  [S0402]  213.9 50.66 0 bottom
PR9014  *0_4/S  [S0402]  211.87 50.6 0 bottom
PR9015  20.5K_1%_4  [R0402]  209.84 49.21 90 bottom
PR9016  *2.2_5%_6  [R0603]  192.44 66.13 90 top
PR9017  6.19K_1%_4  [R0402]  210.47 47.81 0 bottom
PR9018  4.32K_1%_4  [R0402]  212.12 47.97 270 bottom
PR9021  10K_1%_4  [R0402]  202.09 47.33 90 bottom
PR9023  100_1%_4  [R0402]  216.06 84.29 0 bottom
PR9024  16.5K_1%_4  [R0402]  213.14 47.97 90 bottom
PR9025  *Short_0402  [S0402]  204.86 47.05 90 bottom
PR9026  *Short_0402  [S0402]  205.87 47.05 90 bottom
PR9027  309_1%_4  [R0402]  214.15 48.95 270 bottom
PR9028  100_1%_4  [R0402]  217.84 84.29 180 bottom
PR9029  *Short_0402  [S0402]  215.93 54.67 270 bottom
PR9030  1_5%_6  [R0603]  218.09 50.86 180 bottom
PR9032  *Short_0402  [S0402]  219.49 52.89 90 bottom
PR9035  10_1%_6  [R0603]  217.33 56.95 180 bottom
PR9037  10K_1%_4  [R0402]  202.72 45.68 0 bottom
PR9038  *2.2_5%_6  [R0603]  215.75 66.79 0 bottom
PR9040  *1K_1%_4  [R0402]  202.37 49.97 0 bottom
PR9041  *0_5%_4  [R0402]  207.8 55.18 270 top
PR9212  *10K_1%_4  [R0402]  211.87 51.62 180 bottom
PR9213  *12K_1%_4  [R0402]  213.9 51.62 0 bottom
PR9220  8.06K_1%_4  [R0402]  204.5 50.48 0 bottom
PR9222  1K_1%_4  [R0402]  213.9 53.65 0 bottom
PR9501  0_4  [R0402]  196.63 81.27 90 top
PR9502  *Short_0603  [S0603]  198.15 90.74 180 top
PR9503  *Short_0603  [S0603]  191.01 87.49 270 top
PR9504  *1K_1%_4  [R0402]  194.09 80.98 180 top
PR9505  10K_1%_4  [R0402]  204.38 80.45 180 top
PR9506  *0_4/S  [S0402]  204.25 79.31 0 top
PR9507  *0_4/S  [S0402]  204.63 85.18 90 top
PR9508  *Short_0603  [S0603]  197.14 79.69 180 top
PR9509  10K_1%_4  [R0402]  204.38 82.58 180 top
PR9510  6.65K_1%_4  [R0402]  204.38 81.58 0 top
PR9511  *Short_0201  [S0201]  203.99 87.31 90 top
PR9512  *short3720  [SHORT3720]  202.34 90.99 270 top
PR9519  5.6_5%_8  [R0805]  200.51 87.43 0 top
PR9520  1M_5%_4  [R0402]  187.61 72.58 270 top
PR9521  100K_1%_4  [R0402]  188.63 72.58 90 top
PR9522  *0_5%_4  [R0402]  205.39 85.56 180 bottom
PR9802  *0_5%_4  [R0402]  188.7 51.73 90 bottom
PR9803  *0_5%_4  [R0402]  187.74 51.73 90 bottom
PR9805  *short3720  [SHORT3720]  191.42 53.94 180 bottom
PR9806  *short3720  [SHORT3720]  233.84 153.66 180 bottom
PR9807  *0_5%_4  [R0402]  203.56 49.8 0 top
PR9808  *0_5%_4  [R0402]  203.56 51.07 0 top
PR9809  *499_1%_4  [R0402]  196.5 48.99 180 bottom
PR9811  *10K_1%_4  [R0402]  200.31 54.07 180 top
PR9812  *0_5%_4  [R0402]  194.72 48.99 180 bottom
PR9813  *2.2K_5%_4  [R0402]  199.8 50.51 90 bottom
PR9814  *0_5%_4  [R0402]  200.31 53.05 0 bottom
PR9815  *2.2K_5%_4  [R0402]  198.53 49.04 180 bottom
PR9816  *0_5%_4  [R0402]  202.34 55.59 180 top
PR9819  *10K_1%_4  [R0402]  200.31 55.21 0 top
PR9820  *10_5%_6  [R0603]  202.6 53.81 180 top
PR9821  *1_5%_6  [R0603]  200.06 55.59 0 bottom
PR9822  *0_5%_4  [R0402]  200.31 49.04 180 bottom
PR9823  *0_5%_4  [R0402]  200.82 50.51 90 bottom
PR9824  *0_5%_4  [R0402]  200.31 53.05 180 top
PR10000  20K_1%_4  [R0402]  340.52 139.28 270 bottom
PR10001  20K_1%_4  [R0402]  334.55 136.11 0 bottom
PR10002  200K_1%_4  [R0402]  345.24 138.77 90 top
PR10003  200K_1%_4  [R0402]  334.55 134.94 0 bottom
PR10004  10K_1%_4  [R0402]  340.52 137.56 90 bottom
PR10005  10K_1%_4  [R0402]  336.58 140.3 270 bottom
PR10006  10K_1%_4  [R0402]  347.5 139.05 90 top
PR10007  10K_1%_4  [R0402]  334.55 133.85 0 bottom
PR10008  100K_1%_4  [R0402]  338.49 139.33 180 bottom
PR10009  100K_1%_4  [R0402]  332.65 143.68 0 bottom
PR10010  20K_1%_4  [R0402]  344.08 146.52 0 top
PR10011  220K_5%_4  [R0402]  345.52 147.49 180 top
PR10012  549K_1%_4  [R0402]  352 139.79 90 bottom
PR10015  76.8K_1%_4  [R0402]  351.44 138.27 0 bottom
PR10016  100K_1%_4  [R0402]  342.3 146.52 0 top
PR10017  1M_5%_4  [R0402]  350.04 138.39 270 bottom
PR10018  220K_5%_4  [R0402]  352.97 136.23 90 bottom
PR10020  33K_1%_4  [R0402]  348.65 138.77 0 bottom
PR10021  100K_1%_4  [R0402]  349.16 136.62 90 bottom
PR10023  100K_1%_4  [R0402]  345.47 149.06 90 top
PR10024  47K_1%_4  [R0402]  340.32 149.57 0 bottom
PR10025  470K_5%_4  [R0402]  343.49 149.62 180 bottom
PR10026  47K_1%_4  [R0402]  333.2 146.6 0 bottom
PR10027  47K_1%_4  [R0402]  337.7 146.27 180 top
PR10028  470K_5%_4  [R0402]  341.97 149.06 90 top
PR10029  100K_1%_4  [R0402]  337.04 146.5 270 bottom
PR10030  100K_1%_4  [R0402]  337.04 148.35 90 bottom
PR10031  100K_1%_4  [R0402]  336.46 149.7 180 bottom
PR10032  470K_5%_4  [R0402]  338.54 149.57 0 bottom
PR10033  470K_5%_4  [R0402]  334.68 149.57 0 bottom
PR10034  470K_5%_4  [R0402]  335.79 146.39 180 top
PR11000  0.005_1%_12  [R1206]  251.37 21.98 0 bottom
PR11001  *Short_0201  [S0201]  252.06 21.98 0 bottom
PR11002  *Short_0201  [S0201]  250.69 21.98 180 bottom
PR11004  100_1%_4  [R0402]  251.01 11.01 0 bottom
PR11005  100_1%_4  [R0402]  251.01 12.03 0 bottom
PR11006  *0_4/S  [S0402]  251.01 13.04 180 bottom
PR11007  10_5%_8  [R0805]  248.12 17.21 180 top
PR11008  249K_1%_4  [R0402]  255.05 11.39 90 bottom
PR11009  4.02K_1%_4  [R0402]  250.48 12.23 90 top
PR11010  0_5%_6  [R0603]  246.56 17.54 90 bottom
PR11011  0.005_1%_12  [R1206]  218.85 17.49 0 bottom
PR11012  27K_1%_4  [R0402]  256.06 13.55 90 bottom
PR11013  40.2K_1%_4  [R0402]  254.67 9.9 180 bottom
PR11014  *2.2_5%_6  [R0603]  236.23 18.2 270 bottom
PR11015  47K_1%_4  [R0402]  255.05 13.55 270 bottom
PR11016  *Short_0201  [S0201]  219.51 17.49 0 bottom
PR11017  *Short_0201  [S0201]  218.2 17.49 180 bottom
PR11018  *0_4/S  [S0402]  247.86 5.91 90 top
PR11019  *0_4/S  [S0402]  245.5 5.96 90 top
PR11020  *0_4/S  [S0402]  250.91 4.36 0 bottom
PR11021  *0_5%_4  [R0402]  239.43 5.68 180 bottom
PR11022  10_1%_6  [R0603]  240.47 7.71 90 bottom
PR11023  *0_4/S  [S0402]  243.16 9.39 90 bottom
PR11024  0_5%_6  [R0603]  241.08 8.3 0 top
PR11025  22K_1%_4  [R0402]  250.73 8.98 180 bottom
PR11026  0_5%_6  [R0603]  241.33 6.82 0 top
PR11027  2M_1%_4  [R0402]  250.73 10 180 bottom
PR11028  *0_4/S  [S0402]  250.91 5.37 0 bottom
PR11029  *0_4/S  [S0402]  251.62 9.13 270 top
PR11030  10K/F_4  [R0402]  235.62 7.46 270 top
PR11031  47K_1%_4  [R0402]  235.87 8.98 0 bottom
PR11032  *0_5%_4  [R0402]  248.04 8.02 90 top
PR11033  *0_5%_4  [R0402]  246.97 8.02 90 top
PR11034  47K_1%_4  [R0402]  242.86 5.04 90 top
PR11035  249K_1%_4  [R0402]  244.18 7.86 270 top
PR11036  1M_1%_4  [R0402]  243.14 7.86 90 top
PR11037  *0_4/S  [S0402]  241.46 5.3 0 top
PR11038  28K_1%_4  [R0402]  244 9.9 90 top
PR11039  402_1%_4  [R0402]  245.17 7.86 90 top
PR11040  470K_5%_4  [R0402]  227.62 18.38 180 top
PR11041  47K_1%_4  [R0402]  227.62 19.52 0 top
PR11042  100K_1%_4  [R0402]  221.9 17.62 0 top
PR11043  470K_5%_4  [R0402]  222.36 21.07 90 top
PR12000  49.9K_1%_4  [R0402]  258.78 22.57 180 bottom
PR12001  301K_1%_4  [R0402]  260.56 21.55 0 bottom
PR12003  49.9K_1%_4  [R0402]  260.56 22.57 0 bottom
PR12009  *0_4/S  [S0402]  265.84 4.15 270 top
PR12010  *0_4/S  [S0402]  266.86 4.15 270 top
PR12011  *10K_1%_4  [R0402]  270.16 9.74 90 bottom
PR12013  100K_1%_4  [R0402]  225.08 6.95 270 bottom
PR12014  *0_4/S  [S0402]  224.06 6.95 90 bottom
PR12015  100_1%_4  [R0402]  222.16 6.95 270 bottom
PR12016  100_1%_4  [R0402]  220.12 6.95 270 bottom
PR12017  *0_4/S  [S0402]  297.95 39.44 90 top
PR12018  9.09K_1%_4  [R0402]  297.09 41.32 270 top
PR12019  *0_4/S  [S0402]  299.42 40.4 270 top
PR12020  *13K_1%_4  [R0402]  294.55 40.96 180 top
PR12021  *0_4/S  [S0402]  300.56 40.43 270 top
PR12022  1.87K_1%_4  [R0402]  295.31 39.59 270 top
PR12023  *0_5%_4  [R0402]  295.82 38.19 180 top
PR12024  3.32K_1%_4  [R0402]  305.59 41.87 270 top
PR12025  *220K_1%_4  [R0402]  301.73 32.63 0 top
PR12026  100K_1%_4  [R0402]  295.56 32.35 90 top
PR12027  9.09K_1%_4  [R0402]  306.74 41.87 90 top
PR12028  100K_1%_4  [R0402]  296.07 36.79 270 top
PR12029  *130K_1%_4  [R0402]  300.49 34.63 0 top
PR12030  1.87K_1%_4  [R0402]  295.05 36.79 90 top
PR12031  *0_4/S  [S0402]  294.16 39.59 90 top
PR12032  *0_5%_4  [R0402]  295.54 34.23 270 top
PR12034  *549K_1%_4  [R0402]  224.9 12.92 0 top
PR12035  *76.8K_1%_4  [R0402]  226.73 12.89 0 top
PR12036  *220K_1%_4  [R0402]  224.8 14.95 270 top
PR12037  *100K_1%_4  [R0402]  234.25 14.65 90 top
PR13000  3.3_6  [R0603]  195.87 39.08 0 top
PR13001  *0_4/S  [S0402]  199.3 42.64 180 bottom
PR13002  *0_4/P  [R0402]  200.62 42.59 270 top
PR13003  *2.2_6  [R0603]  195.87 37.56 0 top
PR13004  *0_2/S  [S0201]  189.64 42.23 270 bottom
PR13005  *0_4/S  [S0402]  201.63 42.59 90 top
PR13006  *0_4/S  [S0402]  201.71 42.38 90 bottom
PR13007  *0_4/S  [S0402]  200.59 35.63 180 bottom
PR13008  *0_4/S  [S0402]  219.11 40.1 0 bottom
PR13009  3.3_6  [R0603]  221.85 41.75 180 bottom
PR13010  *0_4/P  [R0402]  214.66 40.48 90 bottom
PR13011  *2.2_6  [R0603]  218.5 44.54 90 top
PR13012  *0_2/S  [S0201]  223.14 53.81 0 bottom
PR13013  *0_4/S  [S0402]  215.68 40.48 270 bottom
PR13014  *0_4/S  [S0402]  216.69 40.48 90 bottom
PR13015  *0_4/S  [S0402]  217.63 46.7 0 bottom
PR13016  510K_1%_4  [R0402]  209.2 33.56 180 bottom
PR13017  1_5%_6  [R0603]  214.41 35.4 270 top
PR13018  *0_4/S  [S0402]  211.23 47.59 90 top
PR13019  *2.2_5%_6  [R0603]  213.44 40.05 90 bottom
PR13020  *Short_0201  [S0201]  225.97 35.09 90 bottom
PR13021  *Short_0402  [S0402]  211.61 32.09 90 bottom
PR13022  *0_4/S  [S0402]  212.63 32.22 270 bottom
PR13023  110K_1%_4  [R0402]  209.58 32.09 90 bottom
PR13024  20.5K_1%_4  [R0402]  210.6 32.09 270 bottom
PR13025  *0_5%_4  [R0402]  212.5 30.6 180 bottom
PR13026  *100K_1%_4  [R0402]  214.26 30.6 180 bottom
PR14000  *0_4/S  [S0402]  94.65 66.13 0 top
PR14001  *0_4/S  [S0402]  96.55 63.34 270 bottom
PR14003  1_6  [R0603]  103.28 62.45 0 top
PR14004  *2.2_6  [R0603]  98.33 63.08 90 bottom
PR14005  *0_4/S  [S0402]  94.39 61.3 180 top
PR14006  *0_2/S  [S0201]  102.01 45.91 90 top
PR14007  *0_4/S  [S0402]  101.63 70.83 0 top
PR14008  150K/F_4  [R0402]  101.63 66.77 0 top
PR14009  56K_1%_4  [R0402]  101.63 68.8 0 top
PR14010  *0_4/S  [S0402]  101.63 63.72 0 top
PR14011  10.2K/F_4  [R0402]  101.63 64.73 180 top
PR14012  10K/F_4  [R0402]  93.89 70.45 270 top
PR14013  127K/F_4  [R0402]  92.87 70.45 270 top
PR14014  *0_4/P  [R0402]  99.85 70.45 90 bottom
PR14015  866/F_4  [R0402]  92.49 68.29 270 top
PR14016  *22_5%_4  [R0402]  90.33 63.34 90 top
PR14017  200K/F_4  [R0402]  85.25 62.32 90 top
PR15000  *0_4/S  [S0402]  205.14 31.81 90 bottom
PR15001  *0_4/S  [S0402]  206.53 32.44 180 bottom
PR15002  *0_4/S  [S0402]  206.41 22.54 180 bottom
PR15003  1_6  [R0603]  203.87 30.54 90 bottom
PR15004  *0_4/P  [R0402]  206.41 25.2 0 bottom
PR15005  *2.2_6  [R0603]  203.87 29.68 90 top
PR15006  *0_2/S  [S0201]  191.42 33.7 270 bottom
PR15007  *10K/F_4  [R0402]  205.01 24.95 90 bottom
PR15008  150K/F_4  [R0402]  203.99 24.95 270 bottom
PR15009  *10K/F_4  [R0402]  208.82 24.44 90 bottom
PR15010  *10K/F_4  [R0402]  207.8 24.44 90 bottom
PR15012  *0_4/S  [S0402]  207.93 31.81 90 bottom
PR16000  *0_4/S  [S0402]  290.3 16.14 180 top
PR16001  *0_4/S  [S0402]  290.3 15.13 180 top
PR16004  1_6  [R0603]  292.21 17.67 180 top
PR16005  *2.2_6  [R0603]  295.13 17.29 270 bottom
PR16006  *0_2/S  [S0201]  291.34 24.73 0 top
PR16007  150K/F_4  [R0402]  298.36 16.91 0 top
PR16008  *10K/F_4  [R0402]  298.3 15.89 180 top
PR16009  *10K/F_4  [R0402]  298.18 11.95 180 top
PR16010  10K/F_4  [R0402]  298.18 12.97 180 top
PR16013  *0_4/S  [S0402]  298.81 14.49 270 top
PR16014  *0_4/S  [S0402]  291.19 13.98 180 top
PR16015  *0_4/S  [S0402]  100.92 21.83 270 top
PR16016  *Short_0201  [S0201]  105.04 36.41 270 top
PR16017  88.7K_1%_4  [R0402]  102.27 33.75 90 top
PR16018  *0_4/S  [S0402]  99.9 22.09 270 top
PR16019  100K_1%_4  [R0402]  100.74 33.75 90 top
PR17000  *100K/F_4  [R0402]  189.77 155.41 270 top
PR17001  *100K/F_4  [R0402]  188.75 155.41 90 top
PR17002  *100K/F_4  [R0402]  189.77 153.63 90 top
PR17003  100K/F_4  [R0402]  188.75 153.63 270 top
PR17004  *0_4/P  [R0402]  191.17 153.51 180 top
PR17005  *0_4/P  [R0402]  191.12 154.9 180 top
PR17006  *0_4/S  [S0402]  180.75 150.2 90 bottom
PR17007  *0_4/S  [S0402]  180.63 151.98 90 bottom
PR17009  1_6  [R0603]  182.28 148.55 180 bottom
PR17010  *0_4/S  [S0402]  188.63 152.36 180 bottom
PR17011  *100K/F_4  [R0402]  188.12 149.95 90 bottom
PR17012  *0_4/S  [S0402]  189.14 149.95 90 bottom
PR17013  *2.2_6  [R0603]  184.94 149.19 90 top
PR17014  *0_2/S  [S0201]  190.53 130.11 90 bottom
PR17015  *0_4/S  [S0402]  189.26 148.55 180 bottom
PR17016  *0_4/S  [S0402]  181.39 153.38 180 bottom
PR17017  100/F_4  [R0402]  181.9 151.98 90 bottom
PR17018  *0_4/S  [S0402]  185.58 102.55 0 bottom
PR17019  *0_4/S  [S0402]  185.58 103.56 0 bottom
PR17020  100/F_4  [R0402]  185.58 104.61 0 bottom
PR18000  100K_1%_4  [R0402]  307.12 67.65 0 top
PR18002  1_5%_6  [R0603]  302.17 62.07 180 top
PR18003  *0_4/S  [S0402]  307.88 61.81 0 top
PR18004  *2.2_5%_6  [R0603]  299.37 64.99 0 bottom
PR18005  *Short_0402  [S0402]  307.88 64.86 180 top
PR18006  *0_4/S  [S0402]  286.93 67.4 90 top
PR18008  *0_4/S  [S0402]  307.88 62.83 0 top
PR18009  3.16K_1%_4  [R0402]  308.9 66.89 180 top
PR18010  10K_1%_4  [R0402]  307.52 66.26 270 top
PR18011  *0_5%_4  [R0402]  307.58 60.72 180 top
PR18012  *0_5%_2  [R0201]  310.47 66.64 270 top
PR18013  *0_5%_2  [R0201]  304.58 59.63 180 top
PR18014  *Short_0402  [S0402]  308.9 65.88 0 top
PR19000  4.7_5%_4  [R0402]  133.89 148.17 90 bottom
PR19001  100_1%_4  [R0402]  125.38 154.01 270 top
PR19002  *75_1%_4  [R0402]  126.4 154.01 270 top
PR19003  45.3_1%_4  [R0402]  124.37 154.01 270 top
PR19004  *75_1%_4  [R0402]  127.41 154.01 270 top
PR19005  10K_1%_4  [R0402]  130.46 154.01 90 top
PR19006  4.7K_1%_4  [R0402]  129.45 154.01 90 top
PR19007  4.7K_1%_4  [R0402]  128.43 154.01 90 top
PR19008  2M_1%_4  [R0402]  129.19 144.62 270 top
PR19009  133K_1%_4  [R0402]  129.19 146.39 90 top
PR19010  *0_4/S  [S0402]  132.92 151.47 90 bottom
PR19011  *0_2/S  [S0201]  130.77 154.09 90 bottom
PR19012  *0_5%_2  [R0201]  130.72 153 180 bottom
PR19013  1.5K_1%_2  [R0201]  128.58 142.64 270 bottom
PR19014  *0_2/S  [S0201]  130.03 154.09 270 bottom
PR19015  1.5K_1%_2  [R0201]  129.83 143.22 90 bottom
PR19016  *0_2/S  [S0201]  129.29 154.09 270 bottom
PR19017  *10K_1%_4  [R0402]  124.75 151.98 180 top
PR19018  1.5K_1%_2  [R0201]  131.1 143.22 270 bottom
PR19019  75_1%_4  [R0402]  128.43 154.01 90 bottom
PR19020  1.5K_1%_2  [R0201]  131.99 143.22 90 bottom
PR19021  *0_2/S  [S0201]  126.14 151.98 180 top
PR19022  1.5K_1%_2  [R0201]  133.64 142.97 270 bottom
PR19023  *0_4/S  [S0402]  127.41 154.01 270 bottom
PR19024  1.5K_1%_2  [R0201]  131.22 145.63 180 bottom
PR19025  10_1%_4  [R0402]  126.4 154.01 90 bottom
PR19026  1.4K_1%_4  [R0402]  127.59 143.85 0 bottom
PR19027  *0_5%_2  [R0201]  127.79 141.85 270 bottom
PR19028  49.9_1%_4  [R0402]  125.38 154.01 90 bottom
PR19029  *10K_1%_4  [R0402]  133.94 152.41 90 bottom
PR19030  *0_5%_4  [R0402]  123.35 154.01 270 bottom
PR19031  *0_4/S  [S0402]  123.22 152.26 0 bottom
PR19032  *100_1%_2  [R0201]  160.43 130.39 90 bottom
PR19033  *0_2/S  [S0201]  126.14 142.69 270 bottom
PR19034  100K_1%_4  [R0402]  132.92 153.25 270 bottom
PR19035  *0_2/S  [S0201]  125.25 142.79 270 bottom
PR19036  61.9K_1%_4  [R0402]  124.75 150.97 0 top
PR19037  *100_1%_2  [R0201]  159.42 130.39 90 bottom
PR19038  2.1K_1%_4  [R0402]  124.75 144.49 0 bottom
PR19039  *0_5%_2  [R0201]  124.37 142.79 270 bottom
PR19040  100_1%_2  [R0201]  150.15 130.52 270 bottom
PR19041  28.7K_1%_4  [R0402]  127.16 146.39 90 top
PR19042  *0_2/S  [S0201]  123.22 144.11 270 bottom
PR19043  118K_1%_4  [R0402]  124.75 147.92 0 top
PR19044  *0_2/S  [S0201]  122.33 144.11 270 bottom
PR19045  332K_1%_4  [R0402]  124.75 148.93 0 top
PR19046  100_1%_2  [R0201]  151.8 130.27 0 bottom
PR19047  100/F_4  [R0402]  173.13 130.52 180 bottom
PR19048  *0_4/S  [S0402]  122.13 147.56 0 bottom
PR19049  *0_4/S  [S0402]  122.13 148.58 0 bottom
PR19050  100/F_4  [R0402]  171.36 130.52 0 bottom
PR19052  *0_2/S  [S0201]  132.49 145.25 90 bottom
PR19053  8.2K_1%_4  [R0402]  122.21 145.89 270 bottom
PR19054  *0_5%_4  [R0402]  121.19 145.89 90 bottom
PR19055  9.1K_1%_4  [R0402]  129.83 147.79 180 top
PR19056  49.9K_1%_4  [R0402]  133.76 145.63 180 bottom
PR19057  *0_4/S  [S0402]  135.29 152.8 0 bottom
PR20000  1_5%_6  [R0603]  135.92 150.68 270 bottom
PR20001  *0_2/S  [S0201]  144.56 158.99 270 top
PR20002  *0_2/S  [S0201]  143.03 158.99 270 top
PR20003  *2.2_5%_6  [R0603]  142.02 144.49 0 top
PR20004  *Short_0201  [S0201]  141.76 143.02 90 bottom
PR20005  *Short_0201  [S0201]  141.76 138.55 270 bottom
PR20006  *0_2/S  [S0201]  145.32 156.68 270 top
PR20007  *0_2/S  [S0201]  143.8 158.99 270 top
PR20008  1.33K_1%_4  [R0402]  140.67 142.97 180 top
PR20009  10K_NTC_4_1%  [R0402]  137.07 141.57 90 bottom
PR20010  1.07K_1%_4  [R0402]  138.89 141.57 0 top
PR20011  392_1%_4  [R0402]  141.13 157.95 90 top
PR20012  590_1%_4  [R0402]  138.89 143.6 180 top
PR20013  12K_1%_4  [R0402]  138.89 142.58 0 top
PR20014  392_1%_4  [R0402]  142.15 157.95 90 top
PR20015  1_5%_6  [R0603]  144.81 150.68 270 bottom
PR20016  *0_2/S  [S0201]  152.05 158.96 270 top
PR20017  *2.2_5%_6  [R0603]  149.64 144.24 0 top
PR20018  *Short_0201  [S0201]  149.26 142.97 90 bottom
